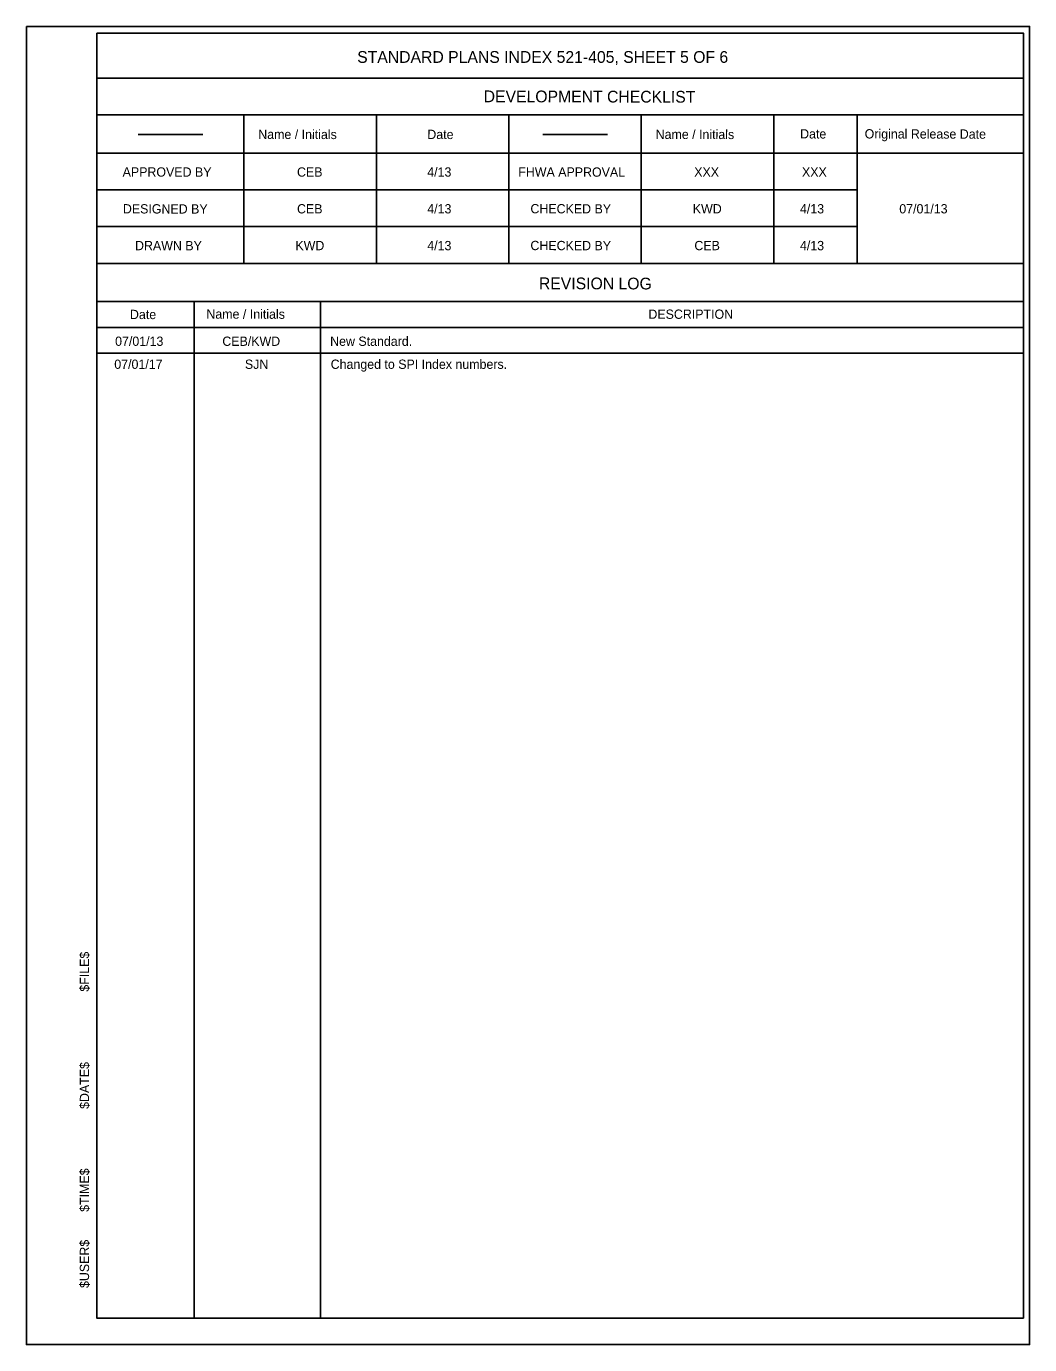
# Model space of a CAD drawing. Extents: x 1.5 to 68.7, y 0 to 31.1.
# Drawn here: x 46.92 to 68.73, y 0 to 28.67 of the extents above; entities that cross this region are included whole.
import ezdxf

# ---------------------------------------------------------------- set-up
doc = ezdxf.new("R2010")
doc.units = 0
for name, color, linetype in [('AdhocPoint_dp', 7, 'Continuous'), ('Border', 7, 'Continuous'), ('SheetBorder_dp', 7, 'Continuous'), ('SheetLines_dp', 7, 'Continuous')]:
    doc.layers.add(name, color=color, linetype=linetype)

msp = doc.modelspace()

# ---------------------------------------------------------------- linework, layer by layer
at = {"layer": 'AdhocPoint_dp'}
for p, q in [((50.751, 26.312), (49.347, 26.312)), ((59.547, 26.312), (58.144, 26.312))]:
    msp.add_line(p, q, dxfattribs=at)
at = {"layer": 'Border'}
for p, q in [((68.593, 27.54), (48.446, 27.54)), ((68.593, 26.74), (48.446, 26.74)), ((51.646, 26.74), (51.646, 23.512)), ((54.526, 26.74), (54.526, 23.512)), ((57.406, 26.74), (57.406, 23.512)), ((60.286, 26.74), (60.286, 23.512)), ((63.166, 26.74), (63.166, 23.512)), ((64.981, 26.74), (64.981, 23.512)), ((68.593, 25.912), (48.446, 25.912)), ((64.981, 25.112), (48.446, 25.112)), ((64.981, 24.312), (48.446, 24.312)), ((68.593, 23.512), (48.446, 23.512)), ((68.593, 22.684), (48.446, 22.684)), ((50.566, 22.684), (50.566, 0.578)), ((53.309, 22.684), (53.309, 0.578)), ((68.593, 22.121), (48.446, 22.121))]:
    msp.add_line(p, q, dxfattribs=at)
msp.add_lwpolyline([(48.446, 28.521), (68.593, 28.521), (68.593, 0.578), (48.446, 0.578)], close=True, dxfattribs=at)
at = {"layer": 'SheetBorder_dp'}
msp.add_line((48.446, 21.557), (68.593, 21.557), dxfattribs=at)
at = {"layer": 'SheetLines_dp'}
msp.add_line((46.915, 0), (46.915, 0), dxfattribs=at)
msp.add_lwpolyline([(46.915, 28.667), (68.729, 28.667), (68.729, 0), (46.915, 0)], close=True, dxfattribs=at)

# ---------------------------------------------------------------- texts
at = {"layer": 'AdhocPoint_dp'}
msp.add_text('New Standard.', height=0.2016, dxfattribs=at).set_placement((53.52, 21.719))
at = {"layer": 'SheetBorder_dp'}
for s, height, p in [('STANDARD PLANS INDEX 521-405, SHEET 5 OF 6', 0.256, (54.108, 27.873)), ('CEB', 0.2016, (52.8, 25.399)), ('4/13', 0.2016, (55.632, 25.399)), ('XXX', 0.2016, (61.436, 25.399)), ('XXX', 0.2016, (63.779, 25.399)), ('CEB', 0.2016, (52.8, 24.599)), ('4/13', 0.2016, (55.632, 24.599)), ('KWD', 0.2016, (61.405, 24.599)), ('4/13', 0.2016, (63.735, 24.599)), ('07/01/13', 0.2016, (65.895, 24.599)), ('KWD', 0.2016, (52.765, 23.799)), ('4/13', 0.2016, (55.632, 23.799)), ('CEB', 0.2016, (61.44, 23.799)), ('4/13', 0.2016, (63.735, 23.799)), ('DESCRIPTION', 0.2016, (60.44, 22.307)), ('07/01/13', 0.2016, (48.845, 21.719)), ('CEB/KWD', 0.2016, (51.176, 21.719)), ('07/01/17', 0.2016, (48.827, 21.219)), ('SJN', 0.2016, (51.667, 21.219)), ('Changed to SPI Index numbers.', 0.2016, (53.532, 21.219))]:
    msp.add_text(s, height=height, dxfattribs=at).set_placement(p)
for s, height, rotation, p in [('DEVELOPMENT CHECKLIST', 0.256, 359.8756, (56.858, 27.017)), ('Name / Initials', 0.2016, 359.8756, (51.957, 26.219)), ('Date', 0.2016, 359.8756, (55.633, 26.217)), ('Name / Initials', 0.2016, 359.8756, (60.597, 26.219)), ('Date', 0.2016, 359.8756, (63.738, 26.229)), ('Original Release Date', 0.2016, 359.8756, (65.142, 26.229)), ('APPROVED BY', 0.2016, 359.8756, (49.008, 25.401)), ('FHWA APPROVAL', 0.2016, 359.8756, (57.611, 25.401)), ('DESIGNED BY', 0.2016, 359.8756, (49.014, 24.599)), ('CHECKED BY', 0.2016, 359.8756, (57.875, 24.601)), ('DRAWN BY', 0.2016, 359.8756, (49.278, 23.799)), ('CHECKED BY', 0.2016, 359.8756, (57.875, 23.801)), ('REVISION LOG', 0.256, 359.8756, (58.059, 22.951)), ('Date', 0.2016, 359.8756, (49.168, 22.302)), ('Name / Initials', 0.2016, 359.8756, (50.829, 22.311)), ('$FILE$', 0.2016, 90, (48.279, 7.675)), ('$DATE$', 0.2016, 90, (48.279, 5.126)), ('$TIME$', 0.2016, 90, (48.279, 2.888)), ('$USER$', 0.2016, 90, (48.279, 1.231))]:
    msp.add_text(s, height=height, rotation=rotation, dxfattribs=at).set_placement(p)

doc.saveas('drawing.dxf')
